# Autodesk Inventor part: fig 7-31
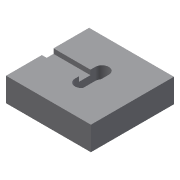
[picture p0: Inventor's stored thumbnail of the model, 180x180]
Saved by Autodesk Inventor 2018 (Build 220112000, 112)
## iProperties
Created: 2004-05
Part Number: fig 7-31
Document SubType Name: Modeling
Designer: CADCIM Technologies
Manufacturer: Standard
Standards Organization: Custom
Density: 1 g/cm^3
Material: Generic
Appearance: Default
Author: CADCIM Technologies
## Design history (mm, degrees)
sketch "Sketch1"
  geometry: L1 (-30.233, -25.517)-(22.302, -25.517); L2 (22.302, -25.517)-(22.302, 25.904); L3 (22.302, 25.904)-(-30.233, 25.904); L4 (-30.233, 25.904)-(-30.233, -25.517)
  constraints: 8 end point, 2 parallel, 1 horizontal, 1 perpendicular
extrude "Extrusion1" new body sketch "Sketch1" distance "d0" = 14.75; taper "d1" = 0 deg
sketch "Sketch2"
  geometry: L1 (1.047, -5.75)-(1.047, 6.846); L2 (-7.35, 6.845)-(-7.35, -5.75); A1 r 4.198 centre (-3.152, 6.846) between (1.047, 6.846) and (-7.35, 6.845); A2 r 4.198 centre (-3.152, -5.75) between (-7.35, -5.75) and (1.047, -5.75)
  constraints: 4 end point, 4 point on circle, 4 tangent, 2 centre point, 1 parallel
extrude "Extrusion2" cut sketch "Sketch2" distance "d2" = 7.5; taper "d3" = 0 deg
sketch "Sketch3"
  geometry: L1 (-7.5, 0)-(-7.5, 12.595) reference; L2 (-7.5, 0)-(0, 0) reference; L3 (-7.5, 2.416)-(-4.537, 2.416); L4 (-4.537, 2.416)-(-4.537, 9.616); L5 (-4.537, 9.616)-(-7.5, 9.616)
  constraints: 6 end point, 2 perpendicular, 2 point on line, 1 parallel
extrude "Extrusion3" cut sketch "Sketch3" extent not by distance; stored distance "d4" = 6.75; taper "d5" = 0 deg
body "Solid1"
